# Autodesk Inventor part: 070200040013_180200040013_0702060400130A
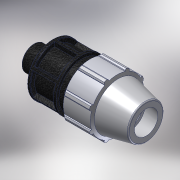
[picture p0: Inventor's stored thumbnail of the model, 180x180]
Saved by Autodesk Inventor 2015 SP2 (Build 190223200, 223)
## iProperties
Created: 2017-02
Part Number: 070200040013_180200040013_0702060400130A
Material: PVC-Piping
Description: PLASSON MALE ADAPTOR 40-1.1/4"
Document SubType Name: Modeling
Designer: KIM
Mass: 92.6774 g
Surface Area: 199.44 cm^2
Volume: 66.1981 cm^3
Density: 1.4 g/cm^3
Appearance: PTFE
Author: KIM
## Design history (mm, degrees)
derived "07020.ipt"
feature "Solid1::07020.ipt"
tag "TaggingFeature1"
body "Solid1"
other parameters: "d4" = 16.71429, "d5" = 29.25, "d7" = 82, "d8" = 61.5, "d9" = 16.71429, "d11" = 3.34286, "d12" = 65.6, "d13" = 120 deg, "d15" = 8 deg, "d16" = 73.8, "d18" = 2, "d19" = 35 deg, "d20" = 17.5 deg, "d21" = 76.26, "d23" = 0, "d25" = 360 deg, "d27" = 1.64, "d34" = 4.1, "d36" = 0, "d42" = 29.25, "d43" = 2.46, "d46" = 1.2, "d51" = 117, "d52" = 22, "d53" = 0.8, "d55" = 360 deg, "d57" = 41.91, "d58" = 29.337, "d59" = 23.4, "E_" = 82, "H_" = 117, "l_2" = 22, "R_" = 41.91
